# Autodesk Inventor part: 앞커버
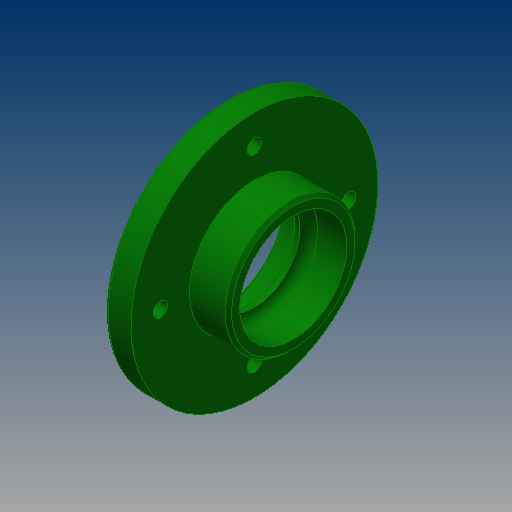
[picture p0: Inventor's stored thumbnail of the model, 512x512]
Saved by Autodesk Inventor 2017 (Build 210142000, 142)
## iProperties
Created: 2015-09
Part Number: 앞커버
Material: 알루미늄 6061
Document SubType Name: Modeling
Designer: mduedu
Density: 2.71 g/cm^3
Mass: 58.9874 g
Surface Area: 98.7754 cm^2
Volume: 21.7666 cm^3
Appearance: 진녹색
Author: mduedu
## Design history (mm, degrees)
sketch "스케치1"
  geometry: L1 (-4, 67)-(-16, 67); L2 (-16, 67)-(-16, 85); L3 (-16, 85)-(-24, 85); L4 (-24, 85)-(-24, 70.5); L5 (-27, 70.5)-(-27, 61); L6 (-27, 61)-(-4, 61); L7 (-4, 61)-(-4, 67); L8 (-79.5, 39.5)-(-79.5, 54.5) reference; L9 (48.5, 54.5)-(48.5, 39.5) reference; L10 (-79.5, 47)-(48.5, 47); L11 (-24, 70.5)-(-27, 70.5); 3 further points
  constraints: 18 end point, 6 parallel, 4 midpoint, 1 horizontal, 1 perpendicular, 1 vertical alignment
  dimensions: "d0" = 23 distance between parallel lines of L7 L5; "d2" = 28 diameter of L6 L10; "d3" = 40 diameter of L1 L10; "d5" = 12 distance of L1.start L1.end; "d6" = 76 diameter of L3 L10; "d7" = 8 distance of L2.end L3.end; "d8" = 47 diameter of L4.end L10
revolve "회전1" sketch "스케치1" stored, may be unused: angle "d4" = 90 deg
sketch "스케치2"
  geometry: C1 r 38 at (0, 0) reference; 2 further points
  constraints: 1 coincident
hole "구멍1" sketch "스케치2" at (0, 0) diameter "d11" = 33; stored, may be unused: countersink angle "d15" = 90 deg, drill point angle "d17" = 0 deg; dims "d12" = 6, "d13" = 4, "d14" = 2, "d16" = 12
fillet "모깎기1" dims "d18" = 3
fillet "모깎기2" dims "d19" = 1
sketch "스케치3"
  geometry: C1 r 38 at (0, 0) reference; 2 further points
  constraints: 1 coincident
hole "구멍2" sketch "스케치3" at (0, 0) diameter "d20" = 40; stored, may be unused: countersink angle "d24" = 90 deg, drill point angle "d26" = 0 deg; dims "d21" = 6, "d22" = 4, "d23" = 2, "d25" = 8.4
fillet "모깎기3" dims "d27" = 0.4
chamfer "모따기1" distance "d28" = 0.8; stored, may be unused: second distance "d29" = 2, angle "d30" = 30 deg
chamfer "모따기2" distance "d61" = 1; stored, may be unused: second distance "d62" = 2, angle "d63" = 45 deg
sketch "스케치7" dims "d56" = 58
  geometry: C1 r 38 at (0, 0) reference; 5 further points
  constraints: 2 vertical alignment, 1 coincident, 7 other
  dimensions: "d59" = 360 deg dimension on C1.centre point (0, 29) (derived)
sketch "스케치8"
  geometry: 4 further points
  constraints: 4 other
hole "구멍5" sketch "스케치8" at (-29, 0), (0, -29), (29, 0), (0, 29) diameter "d64" = 4.5; stored, may be unused: countersink angle "d68" = 90 deg, drill point angle "d70" = 0 deg; dims "d65" = 6, "d66" = 8, "d67" = 4.6, "d69" = 8
chamfer "모따기3" distance "d71" = 1; stored, may be unused: second distance "d72" = 2, angle "d73" = 45 deg
node "솔리드1"
node "참조1"
node "참조2"
